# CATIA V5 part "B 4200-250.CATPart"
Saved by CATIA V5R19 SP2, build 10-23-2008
Part number: B 4200-250
Bounding box of the stored display mesh (mm): x -47.487 to 47.487, y -47.487 to 47.487, z 0 to 620
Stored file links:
  C:\Users\Bora\Desktop\3D Katı model\B serisi\B 4200\B 4200-250.CATPart
  C:\Program Files\Dassault Systemes\B19\intel_a\reffiles\standard\MetricThickPitch.txt
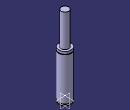
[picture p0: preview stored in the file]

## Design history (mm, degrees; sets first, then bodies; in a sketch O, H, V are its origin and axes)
Body1 (main body)
  Sketch1 on yz-plane, origin (0, 0, 0), H (0, 1, 0), V (0, 0, 1)
    point P1 (47.5, 348.5)
    point P2 (47.5, 343.5)
    point P3 (47.5, 348.5)
    point P6 (47.5, 343.5)
    point P9 (30, 619)
    point P11 (30, 619)
    arc A1 centre (47.5, 346) radius 2.5 from (47.5, 348.5) to (47.5, 343.5) ccw
    line L1 (47.5, 348.5) -> (47.5, 367)
    line L2 (47.5, 13) -> (47.5, 343.5)
    line L3 (43.5, 13) -> (43.5, 8)
    arc A2 centre (29, 619) radius 1 from (30, 619) to (29, 620) ccw
    line L4 (30, 619) -> (30, 367)
    line L5 (47.5, 0) -> (47.5, 8)
    line L6 (29, 620) -> (0, 620)
    point P15 (0, 620)
    line L7 (30, 367) -> (47.5, 367)
    line L8 (0, 0) -> (47.5, 0)
    line L9 (43.5, 13) -> (47.5, 13)
    line L10 (43.5, 8) -> (47.5, 8)
    coincidence: P15 V, P1 P3, P2 P6, P9 P11
    tangency: L6 A2
    horizontal: L7 H, L8 H, L9 H, L10 H
  Shaft1: profile Sketch1, axis Sketch1.V, angle 360
  Sketch2 on face of Shaft1 from Sketch1.L8, origin (0, 0, 0), H (1, 0, 0), V (0, -1, 0)
    point P1 (30, 0)
    distance P1 V = 30
  Hole1: placed by Sketch2, at (30, 0, 0) direction (0, 0, 1), diameter 6.647, depth 13, threaded "M8", thread diameter 8, thread depth 13, pitch 1.25
  CircPattern1: of Hole1, instances 4, angular step 90, axis from xy-plane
